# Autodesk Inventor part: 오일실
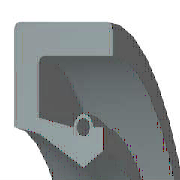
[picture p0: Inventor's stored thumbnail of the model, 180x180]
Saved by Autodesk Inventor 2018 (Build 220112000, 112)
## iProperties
IsCustomPart: 0
Created: 2009-02
Part Number: 오일실
Material: 고무
Description: 오일-실
Document SubType Name: Modeling
Standard: KS B 2804
Standards Organization: KS
Language: ko-KR
Size Designation: S - 17 30 8
Categories: <MemberInstance><Categories><Category DisplayName="샤프트 부품" InternalName="7f7aeb1f-a693-4053-b835-cee3144e0d98" Mnemonic="SHFT"><Category DisplayName="실링" Intern
Density: 0.93 g/cm^3
Appearance: 고무 - 검은색 - 버전 1.1
Author: pww
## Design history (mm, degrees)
revolve "본체" stored, may be unused: angle "d17" = 90 deg
revolve "스프링1" stored, may be unused: angle "d18" = 90 deg
body "Solid1"
sketch "스케치1"
  geometry: L1 (0, 15)-(8, 15); L2 (8, 15)-(8, 13.75); L3 (8, 13.75)-(1.75, 13.75); L4 (0, 15)-(0, 10.6); L5 (0, 10.6)-(1.75, 10.25); L6 (1.75, 10.25)-(4.9, 8.5); L7 (4.9, 8.5)-(0, 8.5); L8 (6.3, 9.375)-(6.3, 10.6); L9 (0, 0)-(9.586, 0) reference; L10 (4.9, 8.5)-(6.3, 9.375); L11 (0, 18)-(0, -3) reference; L12 (-1.917, 0)-(11.503, 0) reference; L13 (4.2, 10.6)-(1.75, 11.09); L14 (1.75, 11.09)-(1.75, 13.75); L15 (6.3, 10.6)-(5.6, 10.6); C1 r 0.455 at (4.9, 10.6); A1 r 0.7 centre (4.9, 10.6) between (5.6, 10.6) and (4.2, 10.6)
  constraints: 26 end point, 5 horizontal alignment, 4 perpendicular, 2 centre point, 2 collinear, 2 horizontal, 2 parallel, 2 point on circle, 2 point on line, 2 vertical alignment, 1 coincident
  dimensions: "d0" = 30 diameter of L1 L9 (= SD2); "d1" = 18.75 diameter of L8.start L9 (= ABDM); "d2" = 1.25 distance of L1.end L2.end (computed from SD); "d3" = 0.91 diameter of C1 (= SPDI); "d4" = 1.4 diameter of A1 (= SPDA); "d5" = 17 diameter of L6.end L9 (= NND); "d6" = 20.5 diameter of L5.end L9 (= TKDM); "d7" = 21.2 diameter of L4.end L9 (= HLDM); "d8" = 4.9 distance from line of C1.centre L4 (= SPDST); "d9" = 6.3 distance between parallel lines of L8 L4 (= SDI); "d10" = 8 distance between parallel lines of L2 L4 (= SWDT); "d12" = 1.75 distance between parallel lines of L14 L4 (= SD)
fillet "모깎기1" dims "d11" = 0.3 (= RR)
other parameters: "SD2" = 30 [user parameter; used in 1 equation term], "SWDT" = 8 [user parameter; used in 1 equation term], "RR" = 0.3 [user parameter; used in 1 equation term], "SD" = 1.75 [user parameter; used in 2 equation terms], "NND" = 17 [user parameter; used in 1 equation term], "SPDA" = 1.4 [user parameter; used in 1 equation term], "SPDI" = 0.91 [user parameter; used in 1 equation term], "TKDM" = 20.5 [user parameter; used in 1 equation term], "HLDM" = 21.2 [user parameter; used in 1 equation term], "ABDM" = 18.75 [user parameter; used in 1 equation term], "SDI" = 6.3 [user parameter; used in 1 equation term], "SPDST" = 4.9 [user parameter; used in 1 equation term], "d13" = 0, "d14" = 0, "d15" = 0, "LAB" = 0.35 [user parameter]
